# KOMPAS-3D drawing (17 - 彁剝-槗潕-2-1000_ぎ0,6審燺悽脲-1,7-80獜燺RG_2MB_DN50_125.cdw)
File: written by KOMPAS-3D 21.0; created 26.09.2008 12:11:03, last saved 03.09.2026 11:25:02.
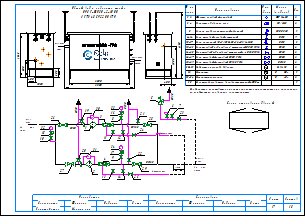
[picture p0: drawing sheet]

Sheets 1-2: A3, landscape

Document properties: Наименование: Макро:21; Автор: RaskoAdmin; Форматы листов документа: 2xA3; Полное имя файла: \\UR38nt01\Departments\КТО\КБ ПУРДГ\Заявки\Прайс-лист на типовые шкафы ГРПШ\ПРДГ_стандарт_20_03_2026\ПРДГ с RG_2MB\ПРДГ-ШУЭО-2-1000_до0,6МПа_Рвых-1,7-80кПа_RG_2MB_DN50_125.cdw

Title block, sheet 1: Наименование: Пункт учета газа / ПУГ-Ш-400-Р / ЛГТИ.485922.001ТУ; designation: ЛГТИ.03.4411141; sheet number: 1; Количество листов документа: 2; organisation: ООО "ЭЛЬСТЕР Газэлектроника"; Форматы листов документа: A3; stored path: C:\Рабочие документы\Компас\ПУГ\Схема.cdw; Разработал: Устинов; Проверил: Кошкин; Утвердил: Кошкин
Title block, sheet 2: sheet number: 2; stored path: D:\Рабочие документы\Заявки\ПУРДГ\ПУРДГ-ШУЭО-2-100-Р 4411220.cdw; designation, second copy: ЛГТИ.03.4411141-

Views: Вид 1, Вид 2
Referenced files: wcvoit.frw
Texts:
  Normal
  Вход
  газа
  PDI
  Выход
  Р=     кПа
  DN125
  DN50
  DN20
  Импульс DN20
  ≥5DN
  HYSWLongFangSong
  № на
  схеме
  Усл.
  обозн.
  Марка
  (модель)
  Кол.
  Фильтр газовый фланцевый
  ФГ 16-50
  Регулятор давления газа
  RG/2MB
  Клапан предохранительный сбросной
  КПС DN20
  Кран шаровой газовый латунный
  DN15
  Кран кнопочный VE-РАСКО-НЗ-1,6-G1/2-М20
  Кран шаровой "под приварку" штуцерный DN20 PN16
  Кран шаровой "под приварку" штуцерный п/п DN20 PN16
  Кран шаровой фланцевый DN50 PN16
  Кран шаровой фланцевый DN125 PN16
  Индикатор перепада давления
  Delta 15
  Манометр
  Манометр-напоромер
  Электрообогреватель взрывозащищенный 400Вт
  0...     МПа
  0...     кПа
  Общий вид и габариты шкафа
  ПРДГ-ШУЭО-2-1000
  Выход газа
  Вход газа
  Р=        МПа
  logo-rasko-ge.png
  Схема открывания дверей
  Предприятие изготовитель может заменять комплектующие на аналогичные,
  не ухудшающие заявленных характеристик.
  Должность
  Конструктор
  Фамилия
  Подпись
  Дата
  Согласовано
  Максимкин
  Лист
  Листов
  POLYLINE_STYLE_0.18_RGB_0_0_0
  POLYLINE_STYLE_0.50_RGB_0_0_0
  POLYLINE_STYLE_0.34_RGB_0_0_0
  PHANTOM_RGB_0_0_0_SC_1_THICK_0.18
  K5LT_THIN_RGB_0_0_0_THICK_0.18
  K5LT32769_RGB_0_0_0_THICK_0.18
  K5LT12_RGB_0_0_0_SC_1_THICK_0.18
  K5LT_DASHED_RGB_0_0_0_SC_1_THICK_0.18
  ACISOTGL_RGB_0_0_0_SC_0.8_THICK_0.25
  CONTINUOUS_RGB_0_127_31_THICK_0.3
  CONTINUOUS_RGB_0_0_255_THICK_0.35
  CONTINUOUS_RGB_255_0_0_THICK_0.35
  POLYLINE_STYLE_0.25_RGB_0_0_0
  CONTINUOUS_RGB_0_0_0_THICK_0.5
  POLYLINE_STYLE_0.35_RGB_0_0_255
  CONTINUOUS_RGB_0_0_0_THICK_0.4
  CONTINUOUS_RGB_0_0_0_THICK_0.35
  Без оформления
Dimensions and other numbers on the sheet: 1; 2; 3; 4; 5; 10; 27; 28; 29; 23; 8; 12; 19; 20; 21; 22; 25; 24; 30; 31; 15; 16; 26; 6; 7; 11; 14; 13; 33; 1, 2; 3, 4; 6-14; 9; 15-17; 18-23; 24-25; 26-27; 28-29; 30-31; 32; 33-34; 35; 400; 1050; 500; 305; 2500; 1565; 2800; 17; 34; 1000; 4130; 18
